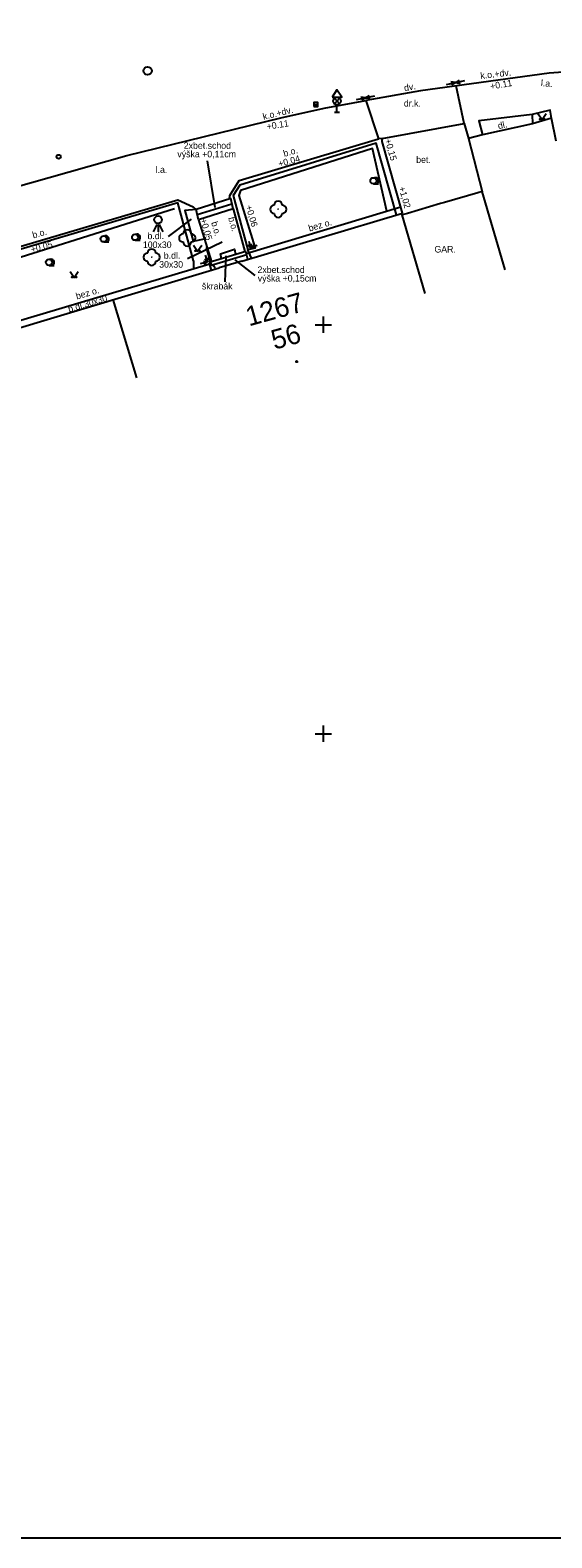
# Model space of a CAD drawing. Extents: x -597333 to -596488, y -1158921 to -1158644.
# Drawn here: x -596692.9 to -596661, y -1158799.2 to -1158707 of the extents above; entities that cross this region are included whole.
import ezdxf

# ---------------------------------------------------------------- set-up
doc = ezdxf.new("R2010")
doc.units = 0
for name, color, linetype in [('Vrstva 1', 7, 'Continuous'), ('Vrstva 10', 7, 'Continuous'), ('Vrstva 11', 7, 'Continuous'), ('Vrstva 14', 7, 'Continuous'), ('Vrstva 15', 7, 'Continuous'), ('Vrstva 17', 7, 'Continuous'), ('Vrstva 22', 7, 'Continuous'), ('Vrstva 24', 7, 'Continuous'), ('Vrstva 25', 7, 'Continuous'), ('Vrstva 4', 7, 'Continuous'), ('Vrstva 43', 7, 'Continuous'), ('Vrstva 44', 7, 'Continuous'), ('Vrstva 49', 7, 'Continuous'), ('Vrstva 5', 7, 'Continuous'), ('Vrstva 50', 7, 'Continuous'), ('Vrstva 62', 7, 'Continuous'), ('Vrstva 7', 7, 'Continuous'), ('Vrstva 9', 7, 'Continuous')]:
    doc.layers.add(name, color=color, linetype=linetype)

msp = doc.modelspace()

# ---------------------------------------------------------------- linework, layer by layer
at = {"layer": 'Vrstva 1'}
msp.add_lwpolyline([(-596698.148, -1158650.657), (-596698.148, -1158799.157), (-596488.148, -1158799.157), (-596488.148, -1158650.657)], close=True, dxfattribs=at)
at = {"layer": 'Vrstva 10'}
for p, q in [((-596661.05, -1158712.38), (-596662.21, -1158712.72)), ((-596660.76, -1158713.78), (-596661.05, -1158712.38)), ((-596665.27, -1158713.39), (-596666.12, -1158713.61)), ((-596666.12, -1158713.61), (-596665.29, -1158716.85))]:
    msp.add_line(p, q, dxfattribs=at)
at = {"layer": 'Vrstva 11'}
for points in [[(-596671.12, -1158718.05), (-596671.99, -1158714.22), (-596680.05, -1158716.79), (-596680.15, -1158717.09), (-596679.16, -1158720.31), (-596679.61, -1158720.41)], [(-596684.09, -1158717.92), (-596697.28, -1158722.07), (-596696.76, -1158725.45), (-596697.07, -1158725.6)]]:
    msp.add_lwpolyline(points, dxfattribs=at)
at = {"layer": 'Vrstva 14'}
for p, q in [((-596671.93, -1158716.388), (-596671.618, -1158716.388)), ((-596688.41, -1158719.938), (-596688.098, -1158719.938)), ((-596686.49, -1158719.838), (-596686.177, -1158719.838)), ((-596691.75, -1158721.368), (-596691.438, -1158721.368))]:
    msp.add_line(p, q, dxfattribs=at)
for points in [[(-596661.882, -1158712.08), (-596661.632, -1158712.455), (-596661.382, -1158712.08)], [(-596682.925, -1158720.129), (-596682.675, -1158720.504), (-596682.425, -1158720.129)], [(-596690.461, -1158721.736), (-596690.211, -1158722.111), (-596689.961, -1158721.736)]]:
    msp.add_lwpolyline(points, dxfattribs=at)
for centre, radius in [((-596661.757, -1158712.43), 0.025), ((-596661.507, -1158712.43), 0.025), ((-596671.93, -1158716.2), 0.188), ((-596677.75, -1158717.94), 0.00025), ((-596688.41, -1158719.75), 0.188), ((-596686.49, -1158719.65), 0.188), ((-596683.31, -1158719.69), 0.00025), ((-596685.48, -1158720.87), 0.00025), ((-596682.8, -1158720.479), 0.025), ((-596682.55, -1158720.479), 0.025), ((-596691.75, -1158721.18), 0.188), ((-596690.336, -1158722.086), 0.025), ((-596690.086, -1158722.086), 0.025)]:
    msp.add_circle(centre, radius, dxfattribs=at)
for centre, radius, start, end in [((-596671.805, -1158716.2), 0.188, 249.49437, 109.04743), ((-596678, -1158717.94), 0.25, 89.99999, 269.99999), ((-596677.75, -1158717.69), 0.25, 0, 179.99999), ((-596677.75, -1158718.19), 0.25, 179.99999, 359.99999), ((-596677.5, -1158717.94), 0.25, 270, 89.99999), ((-596688.285, -1158719.75), 0.188, 249.49437, 109.04743), ((-596686.365, -1158719.65), 0.188, 249.49437, 109.04743), ((-596683.56, -1158719.69), 0.25, 89.99999, 269.99999), ((-596683.31, -1158719.44), 0.25, 0, 179.99999), ((-596683.31, -1158719.94), 0.25, 179.99999, 359.99999), ((-596683.06, -1158719.69), 0.25, 270, 89.99999), ((-596685.73, -1158720.87), 0.25, 89.99999, 269.99999), ((-596685.48, -1158720.62), 0.25, 0, 179.99999), ((-596685.23, -1158720.87), 0.25, 270, 89.99999), ((-596691.625, -1158721.18), 0.188, 249.49437, 109.04743), ((-596685.48, -1158721.12), 0.25, 179.99999, 359.99999)]:
    msp.add_arc(centre, radius, start, end, dxfattribs=at)
at = {"layer": 'Vrstva 15'}
msp.add_line((-596682.695, -1158718.265), (-596680.575, -1158717.605), dxfattribs=at)
for points in [[(-596680.5, -1158717.92), (-596680.65, -1158717.29), (-596682.77, -1158717.95)], [(-596680.5, -1158717.92), (-596682.62, -1158718.58), (-596682.77, -1158717.95)]]:
    msp.add_lwpolyline(points, dxfattribs=at)
msp.add_circle((-596676.614, -1158727.253), 0.0438, dxfattribs=at)
at = {"layer": 'Vrstva 17'}
msp.add_lwpolyline([(-596670.15, -1158718.18), (-596671.39, -1158713.79), (-596671.39, -1158713.62), (-596671.62, -1158713.64)], dxfattribs=at)
at = {"layer": 'Vrstva 22'}
msp.add_lwpolyline([(-596681.6, -1158721.55), (-596681.69, -1158721.41), (-596681.85, -1158721.28), (-596682.13, -1158720.28)], dxfattribs=at)
at = {"layer": 'Vrstva 24'}
msp.add_circle((-596691.16, -1158714.73), 0.125, dxfattribs=at)
at = {"layer": 'Vrstva 25'}
msp.add_line((-596675.575, -1158711.54), (-596675.325, -1158711.54), dxfattribs=at)
msp.add_lwpolyline([(-596675.575, -1158711.666), (-596675.325, -1158711.666), (-596675.325, -1158711.415), (-596675.575, -1158711.415)], close=True, dxfattribs=at)
msp.add_circle((-596685.73, -1158709.48), 0.25, dxfattribs=at)
at = {"layer": 'Vrstva 4'}
for p, q in [((-596663.878, -1158721.646), (-596665.29, -1158716.85)), ((-596679.971, -1158721.116), (-596670.15, -1158718.18)), ((-596668.768, -1158723.086), (-596670.18, -1158718.29)), ((-596697.471, -1158726.348), (-596681.356, -1158721.53)), ((-596686.392, -1158728.254), (-596687.824, -1158723.464))]:
    msp.add_line(p, q, dxfattribs=at)
for points in [[(-596665.29, -1158716.85), (-596665.558, -1158716.929)], [(-596669.859, -1158718.195), (-596670.18, -1158718.29), (-596670.15, -1158718.18)], [(-596667.584, -1158717.526), (-596667.828, -1158717.597)], [(-596679.73, -1158720.519), (-596681.958, -1158721.188)], [(-596679.67, -1158720.735), (-596681.899, -1158721.404)], [(-596679.595, -1158721.004), (-596679.73, -1158720.519)], [(-596681.826, -1158721.671), (-596681.958, -1158721.188)]]:
    msp.add_lwpolyline(points, dxfattribs=at)
at = {"layer": 'Vrstva 44'}
for p, q in [((-596674.01, -1158711.15), (-596674.31, -1158711.494)), ((-596674.31, -1158711.15), (-596674.01, -1158711.494)), ((-596674.16, -1158712), (-596674.16, -1158711.55)), ((-596674.31, -1158712), (-596674.01, -1158712)), ((-596685.164, -1158718.873), (-596685.39, -1158719.325)), ((-596685.09, -1158718.875), (-596685.09, -1158719.325)), ((-596685.015, -1158718.873), (-596684.79, -1158719.325))]:
    msp.add_line(p, q, dxfattribs=at)
msp.add_lwpolyline([(-596674.46, -1158711.094), (-596673.86, -1158711.094), (-596674.16, -1158710.644), (-596674.46, -1158711.094)], dxfattribs=at)
for centre, radius in [((-596674.16, -1158711.322), 0.228), ((-596685.09, -1158718.58), 0.234)]:
    msp.add_circle(centre, radius, dxfattribs=at)
at = {"layer": 'Vrstva 49'}
for p, q in [((-596667.468, -1158710.306), (-596666.914, -1158710.2)), ((-596666.914, -1158710.2), (-596667.193, -1158710.157)), ((-596666.914, -1158710.2), (-596667.155, -1158710.346)), ((-596666.917, -1158710.203), (-596666.676, -1158710.057)), ((-596666.36, -1158710.096), (-596666.914, -1158710.201)), ((-596666.914, -1158710.2), (-596666.634, -1158710.243)), ((-596672.973, -1158711.227), (-596672.419, -1158711.121)), ((-596672.419, -1158711.121), (-596672.699, -1158711.078)), ((-596672.419, -1158711.121), (-596672.661, -1158711.266)), ((-596672.423, -1158711.124), (-596672.181, -1158710.978)), ((-596671.866, -1158711.017), (-596672.42, -1158711.122)), ((-596672.419, -1158711.121), (-596672.14, -1158711.164)), ((-596681.605, -1158717.83), (-596682.06, -1158714.971)), ((-596684.449, -1158719.605), (-596683.047, -1158718.554)), ((-596681.177, -1158719.949), (-596683.289, -1158720.966)), ((-596682.046, -1158720.905), (-596682.071, -1158721.154)), ((-596679.602, -1158720.109), (-596679.444, -1158720.302)), ((-596679.397, -1158720.056), (-596679.444, -1158720.302)), ((-596679.264, -1158720.128), (-596679.444, -1158720.302)), ((-596679.195, -1158720.328), (-596679.444, -1158720.302)), ((-596682.317, -1158721.108), (-596682.071, -1158721.154)), ((-596682.265, -1158721.313), (-596682.071, -1158721.154)), ((-596682.245, -1158720.975), (-596682.071, -1158721.154)), ((-596679.151, -1158721.987), (-596680.375, -1158721.03))]:
    msp.add_line(p, q, dxfattribs=at)
for points in [[(-596679.551, -1158719.882), (-596679.444, -1158720.302)], [(-596682.214, -1158720.744), (-596682.071, -1158721.154)], [(-596680.959, -1158720.791), (-596681.009, -1158722.375)], [(-596679.033, -1158720.16), (-596679.444, -1158720.302)], [(-596682.492, -1158721.262), (-596682.071, -1158721.154)]]:
    msp.add_lwpolyline(points, dxfattribs=at)
at = {"layer": 'Vrstva 5'}
for p, q in [((-596662.21, -1158712.72), (-596665.27, -1158713.39)), ((-596665.558, -1158716.929), (-596667.584, -1158717.526)), ((-596667.828, -1158717.597), (-596669.859, -1158718.195)), ((-596679.372, -1158720.937), (-596679.61, -1158720.41)), ((-596682.93, -1158721.1), (-596682.92, -1158721.55)), ((-596679.971, -1158721.116), (-596681.356, -1158721.53))]:
    msp.add_line(p, q, dxfattribs=at)
at = {"layer": 'Vrstva 62'}
for p, q in [((-596675, -1158724.5), (-596675, -1158725.5)), ((-596675.5, -1158725), (-596674.5, -1158725)), ((-596675, -1158749.5), (-596675, -1158750.5)), ((-596675.5, -1158750), (-596674.5, -1158750))]:
    msp.add_line(p, q, dxfattribs=at)
at = {"layer": 'Vrstva 7'}
for p, q in [((-596672.4, -1158711.29), (-596671.62, -1158713.64)), ((-596662.24, -1158712.15), (-596662.21, -1158712.72)), ((-596680.5, -1158717.92), (-596679.79, -1158720.53)), ((-596682.62, -1158718.58), (-596681.83, -1158721.15)), ((-596697.28, -1158725.86), (-596681.932, -1158721.281))]:
    msp.add_line(p, q, dxfattribs=at)
for points in [[(-596641.141, -1158709.139), (-596642, -1158709.1), (-596648.21, -1158708.88), (-596651.79, -1158708.95), (-596661.19, -1158709.61), (-596669.062, -1158710.691), (-596672.4, -1158711.29)], [(-596671.39, -1158713.62), (-596666.39, -1158712.7), (-596666.879, -1158710.391)], [(-596719.98, -1158724.4), (-596710.3, -1158721.48), (-596694.04, -1158716.65), (-596687, -1158714.66), (-596677.59, -1158712.36), (-596674.94, -1158711.76), (-596672.4, -1158711.29)], [(-596661.05, -1158712.38), (-596661.13, -1158711.88), (-596662.24, -1158712.15), (-596665.49, -1158712.53), (-596665.27, -1158713.39)], [(-596666.39, -1158712.7), (-596666.12, -1158713.61)], [(-596680.73, -1158717.315), (-596680.71, -1158717.1), (-596680.14, -1158716.19), (-596671.62, -1158713.64)], [(-596697.28, -1158725.86), (-596698.35, -1158722.12), (-596698.02, -1158721.54), (-596683.88, -1158717.36), (-596682.94, -1158717.79), (-596682.77, -1158717.95)], [(-596682.77, -1158717.95), (-596683.45, -1158718.01), (-596682.94, -1158719.9), (-596682.261, -1158719.748)], [(-596679.697, -1158720.637), (-596670.26, -1158717.791)], [(-596681.219, -1158720.966), (-596681.28, -1158720.67), (-596680.41, -1158720.38), (-596680.356, -1158720.707)]]:
    msp.add_lwpolyline(points, dxfattribs=at)
at = {"layer": 'Vrstva 9'}
for points in [[(-596670.52, -1158718.28), (-596671.76, -1158713.9), (-596680.1, -1158716.46), (-596680.51, -1158717.09), (-596679.61, -1158720.41)], [(-596682.93, -1158721.1), (-596683.89, -1158717.54), (-596697.81, -1158721.66), (-596698.13, -1158722.26), (-596697.14, -1158725.52)]]:
    msp.add_lwpolyline(points, dxfattribs=at)

# ---------------------------------------------------------------- texts
at = {"layer": 'Vrstva 43'}
for s, p in [('1267', (-596679.536, -1158725.104)), ('56', (-596677.983, -1158726.534))]:
    msp.add_text(s, height=1.2, rotation=15.52539, dxfattribs=at).set_placement(p)
at = {"layer": 'Vrstva 49'}
for s, rotation, p in [('k.o.+dv.', 6.51552, (-596665.375, -1158709.975)), ('dv.', 10.16865, (-596670.026, -1158710.726)), ('l.a.', 355.21407, (-596661.712, -1158710.408)), ('k.o.+dv.', 13.73499, (-596678.64, -1158712.482)), ('dl.', 12.86354, (-596664.282, -1158713.047)), ('b.o.', 15.37266, (-596677.378, -1158714.733)), ('b.o.', 285.70864, (-596681.852, -1158718.752)), ('b.o.', 285.70864, (-596680.806, -1158718.472)), ('bez o.', 15.9106, (-596675.837, -1158719.302)), ('b.o.', 15.37266, (-596692.711, -1158719.722)), ('b.dl.30x30', 16.64423, (-596690.523, -1158724.244)), ('bez o.', 15.9106, (-596690.051, -1158723.458))]:
    msp.add_text(s, height=0.4, rotation=rotation, dxfattribs=at).set_placement(p)
for s, p in [('dr.k.', (-596670.072, -1158711.66)), ('2xbet.schod', (-596683.519, -1158714.245)), ('l.a.', (-596685.239, -1158715.714)), ('bet.', (-596669.318, -1158715.105)), ('100x30', (-596686.017, -1158720.31)), ('b.dl.', (-596685.737, -1158719.767)), ('b.dl.', (-596684.74, -1158720.968)), ('GAR.', (-596668.204, -1158720.584)), ('30x30', (-596685.021, -1158721.511)), ('2xbet.schod', (-596679.014, -1158721.837)), ('škrabák', (-596682.41, -1158722.841))]:
    msp.add_text(s, height=0.4, dxfattribs=at).set_placement(p)
at = {"layer": 'Vrstva 50'}
for s, rotation, p in [('+0.11', 9.414, (-596664.764, -1158710.623)), ('+0.11', 9.414, (-596678.418, -1158713.087)), ('+0,15', 285.70864, (-596671.243, -1158713.701)), ('+0,04', 15.37266, (-596677.683, -1158715.371)), ('+1,02', 285.70864, (-596670.392, -1158716.615)), ('+0,06', 285.70864, (-596679.739, -1158717.75)), ('+0,05', 285.70864, (-596682.516, -1158718.574)), ('+0,05', 15.37266, (-596692.805, -1158720.605))]:
    msp.add_text(s, height=0.4, rotation=rotation, dxfattribs=at).set_placement(p)
for s, p in [('výška +0,11cm', (-596683.908, -1158714.766)), ('výška +0,15cm', (-596678.996, -1158722.358))]:
    msp.add_text(s, height=0.4, dxfattribs=at).set_placement(p)

doc.saveas('drawing.dxf')
